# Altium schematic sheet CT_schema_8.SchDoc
size 385 x 278 mm
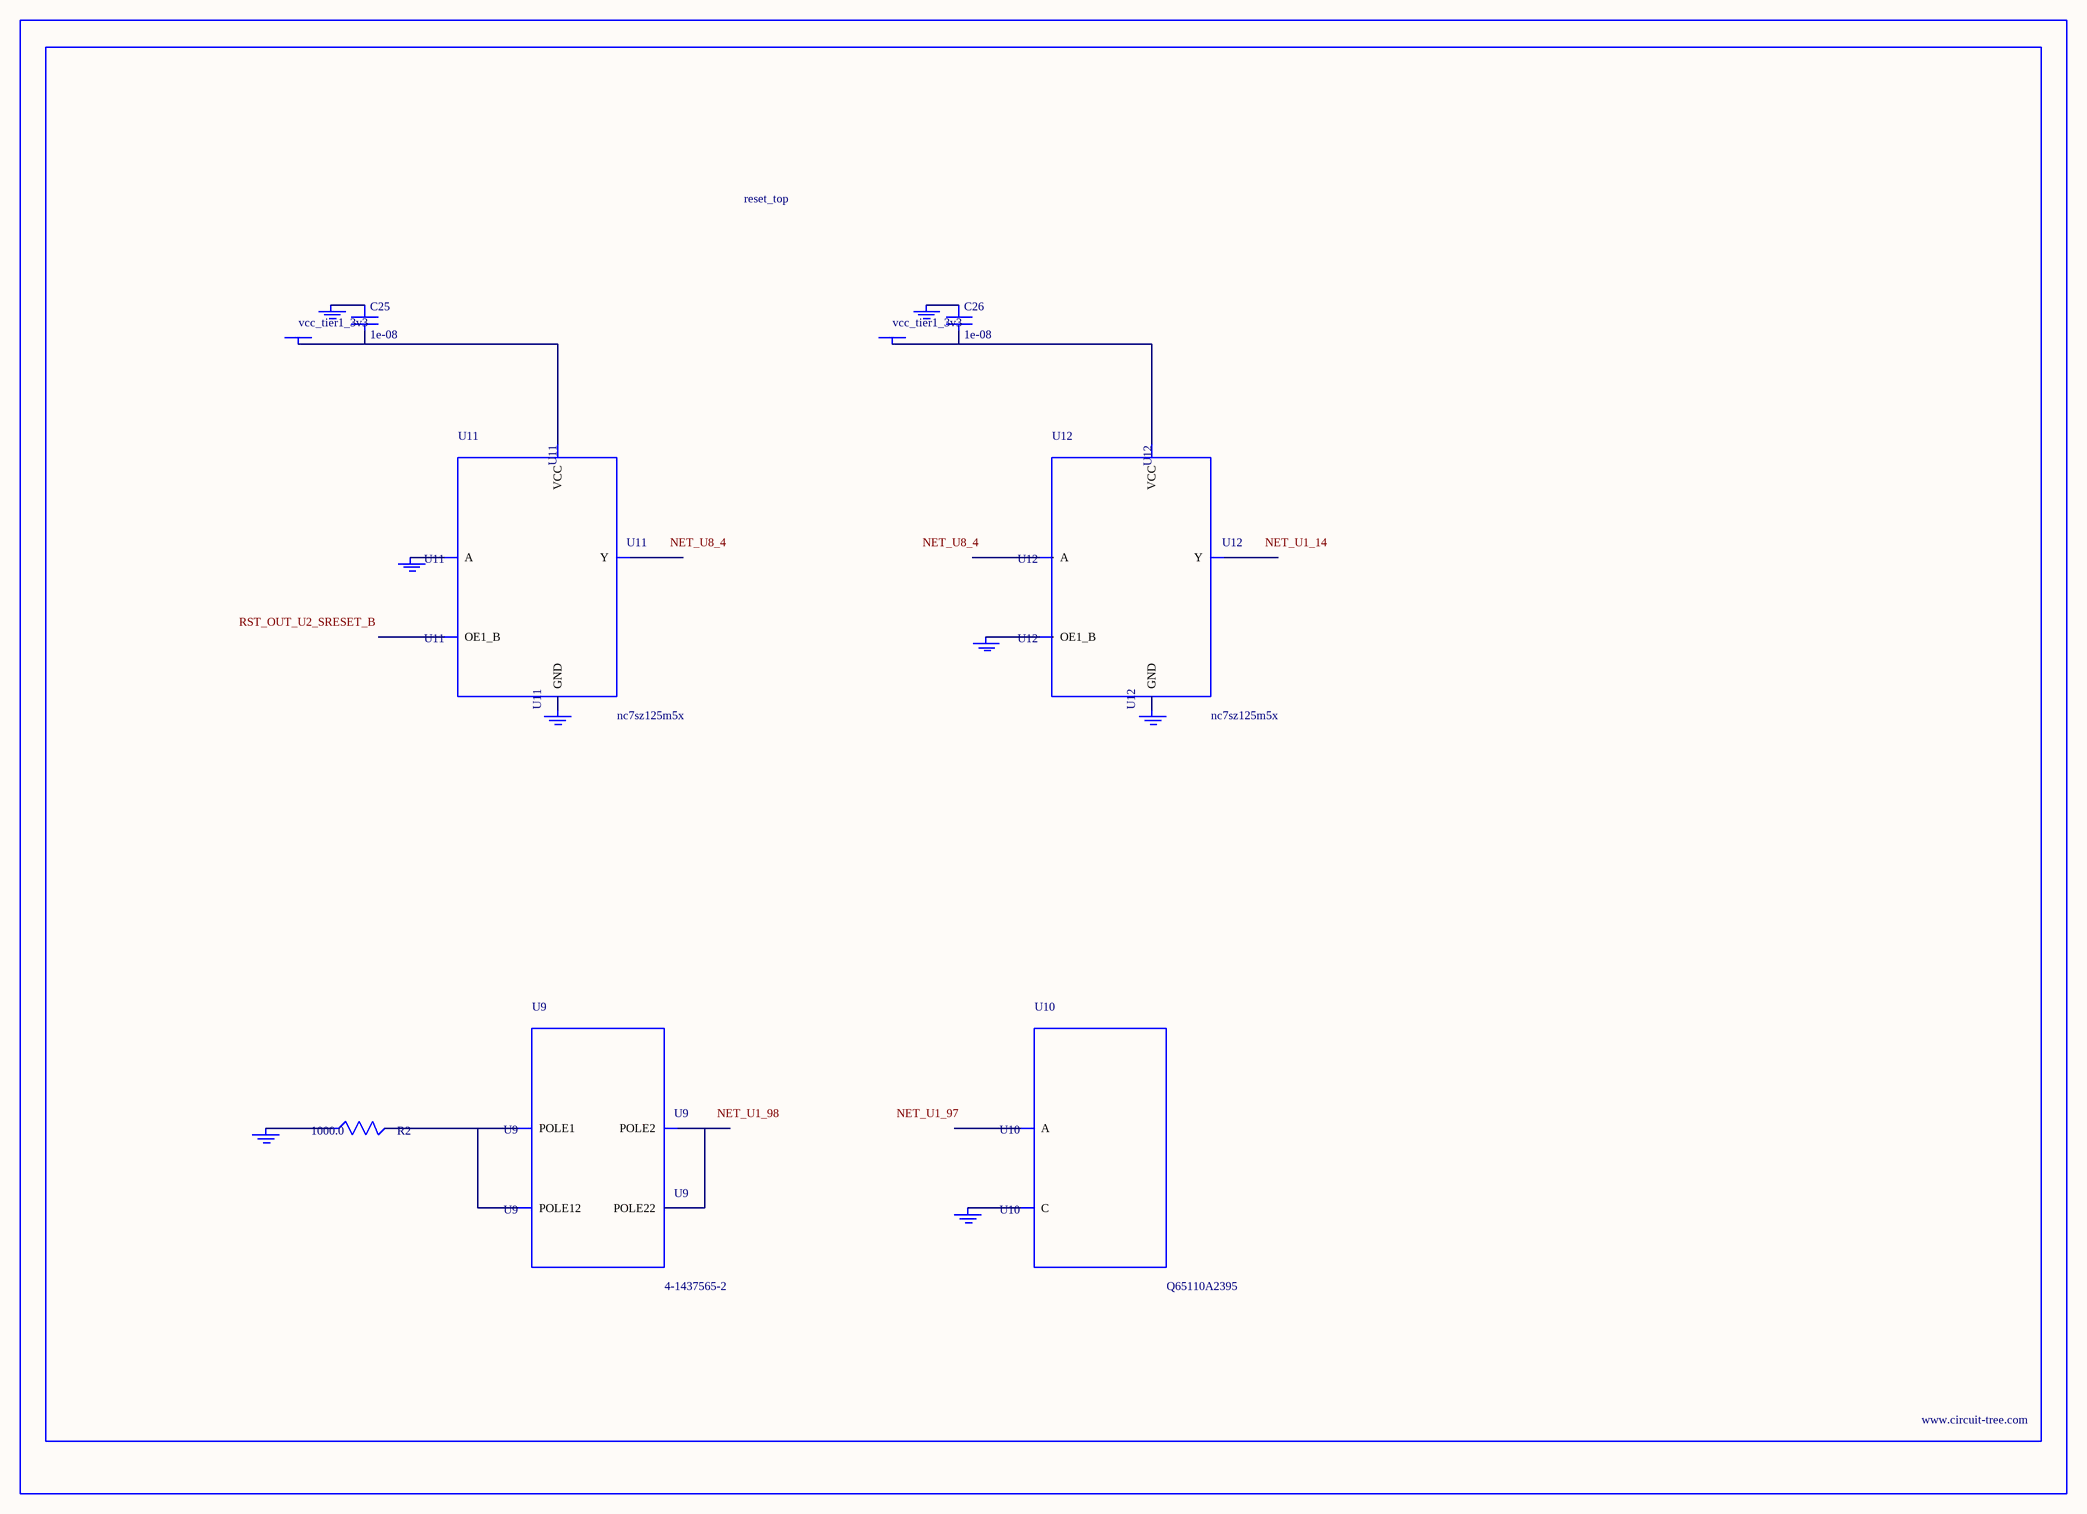
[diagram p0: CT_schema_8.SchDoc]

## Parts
BORDER7  (no value)
C25  1e-08  [C0402]
C26  1e-08  [C0402]
GND_INSTANCE_7_0  (no value)
GND_INSTANCE_7_1  (no value)
GND_INSTANCE_7_2  (no value)
GND_INSTANCE_7_3  (no value)
GND_INSTANCE_7_4  (no value)
GND_INSTANCE_7_5  (no value)
GND_INSTANCE_7_6  (no value)
GND_INSTANCE_7_7  (no value)
POWER_INSTANCE_7_0  vcc_tier1_3v3
POWER_INSTANCE_7_1  vcc_tier1_3v3
R2  1000.0  [R0603]
U9  4-1437565-2  [SW_4-1437565-2]
U10  Q65110A2395  [LGM67K-G1J2-24-Z]
U11  nc7sz125m5x  [NC7SZ125M5X]
U12  nc7sz125m5x  [NC7SZ125M5X]

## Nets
NetC25_1: C25.1 GND_INSTANCE_7_2.0(GND)
NetC25_2: C25.2 POWER_INSTANCE_7_0.0(PWR) U11.5(VCC)
NetC26_1: C26.1 GND_INSTANCE_7_5.0(GND)
NetC26_2: C26.2 POWER_INSTANCE_7_1.0(PWR) U12.5(VCC)
NetGND_INSTANCE_7_0_0: GND_INSTANCE_7_0.0(GND) R2.1
NetGND_INSTANCE_7_1_0: GND_INSTANCE_7_1.0(GND) U10.C
NetGND_INSTANCE_7_3_0: GND_INSTANCE_7_3.0(GND) U11.2(A)
NetGND_INSTANCE_7_4_0: GND_INSTANCE_7_4.0(GND) U11.3(GND)
NetGND_INSTANCE_7_6_0: GND_INSTANCE_7_6.0(GND) U12.1(OE1_B)
NetGND_INSTANCE_7_7_0: GND_INSTANCE_7_7.0(GND) U12.3(GND)
NetR2_2: R2.2 U9.1(POLE1) U9.2(POLE12)
NetU9_3: U9.3(POLE2) U9.4(POLE22)

Not connected (* = marked no-connect by the designer): U10 A; U11 1(OE1_B) 4(Y); U12 2(A) 4(Y)

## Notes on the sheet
- Labels drawn without touching a wire or pin: NET_U1_14, NET_U1_97, NET_U1_98, NET_U8_4, RST_OUT_U2_SRESET_B

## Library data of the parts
BORDER7 = BORDER_PAGE7
C25 C26 = C0402C103K3RAC
GND_INSTANCE_7_0-GND_INSTANCE_7_7 = GND
POWER_INSTANCE_7_0 POWER_INSTANCE_7_1 = PWR
R2 = RC0603JR-071KL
